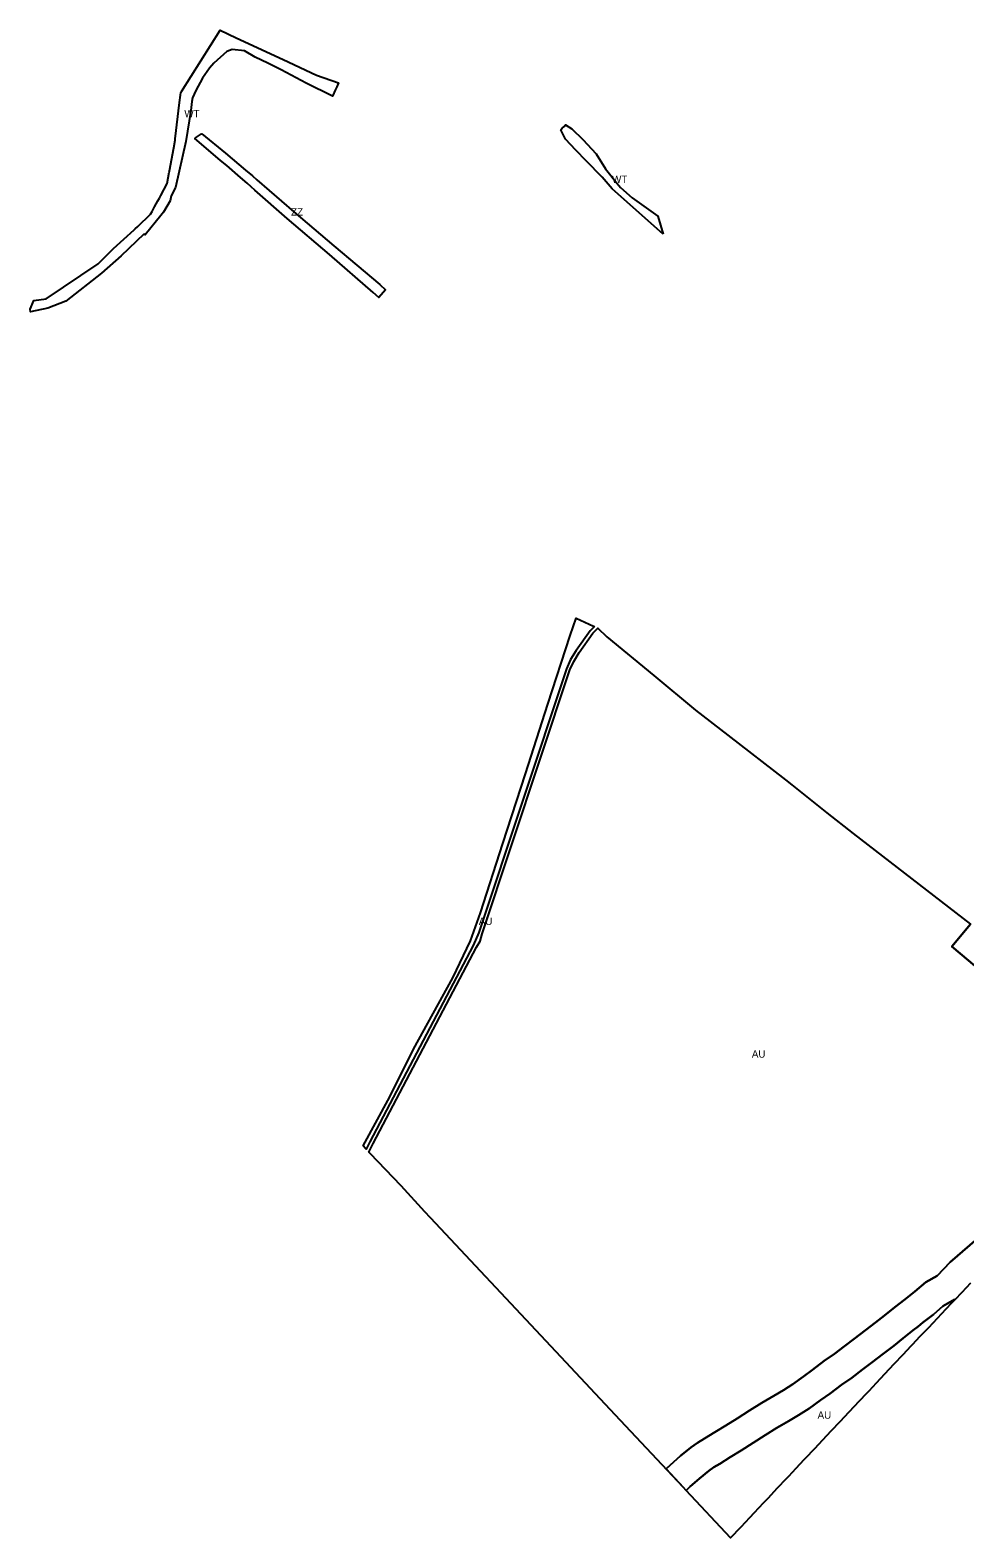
# Model space of a CAD drawing. Extents: x -537068 to -534056, y -1176840 to -1172401.
# Drawn here: x -536870 to -536233, y -1176528 to -1175501 of the extents above; entities that cross this region are included whole.
import ezdxf

# ---------------------------------------------------------------- set-up
doc = ezdxf.new("R2010")
doc.units = 0
for name, color, linetype in [('90640013', 7, 'Continuous'), ('90670013', 7, 'Continuous'), ('90710023', 7, 'Continuous'), ('90750013', 7, 'Continuous')]:
    doc.layers.add(name, color=color, linetype=linetype)

msp = doc.modelspace()

# ---------------------------------------------------------------- linework, layer by layer
at = {"layer": '90640013'}
for points in [[(-536759.14, -1175546.95), (-536759.43, -1175549.31), (-536760.2, -1175555.61), (-536763.62, -1175576.6), (-536770.63, -1175607.96), (-536773.63, -1175613.72), (-536774.37, -1175617.09), (-536778.85, -1175624.83), (-536780.67, -1175627.12), (-536791.22, -1175640.34), (-536792.15, -1175639.9), (-536807.7, -1175654.66), (-536820.95, -1175666.33), (-536845.3, -1175685.5), (-536857.62, -1175690.33), (-536869.36, -1175692.85), (-536869.69, -1175690.99), (-536867.27, -1175684.92), (-536858.75, -1175683.8), (-536823.33, -1175660), (-536822.48, -1175659.15), (-536818.75, -1175655.44), (-536812.82, -1175649.52), (-536798.75, -1175636.8), (-536798, -1175636.09), (-536796.36, -1175634.54), (-536787.59, -1175626.26), (-536786.55, -1175624.33), (-536784.89, -1175621.26), (-536782.61, -1175617.04), (-536781.63, -1175615.22), (-536780.65, -1175613.4), (-536776.23, -1175605.22), (-536774.85, -1175597.57), (-536774.78, -1175597.19), (-536774.66, -1175596.55), (-536771.82, -1175580.92), (-536770.88, -1175575.77), (-536770.77, -1175574.85), (-536767.84, -1175550.16), (-536767.24, -1175545.07), (-536766.92, -1175543.35), (-536766.47, -1175542.55), (-536740.27, -1175500.8), (-536729.21, -1175505.96), (-536697.28, -1175520.87), (-536674.62, -1175531.43), (-536659.47, -1175536.67), (-536660.75, -1175539.52), (-536661.77, -1175541.78), (-536663.39, -1175545.39), (-536663.63, -1175545.89), (-536681.48, -1175536.89), (-536698.55, -1175527.89), (-536707.77, -1175523.22), (-536716.27, -1175519.21), (-536723.7, -1175514.8), (-536732.11, -1175514.02), (-536735.71, -1175515.33), (-536744.58, -1175523.27), (-536747.34, -1175526.78), (-536752.18, -1175533.41), (-536756.67, -1175542.01)], [(-536438.2, -1175639.85), (-536473.11, -1175608.92), (-536479.81, -1175600.97), (-536490.76, -1175589.93), (-536497.76, -1175582.55), (-536504.76, -1175575.16), (-536507.91, -1175568.69), (-536507.02, -1175567.7), (-536505.83, -1175566.38), (-536504.84, -1175565.28), (-536500.44, -1175568.03), (-536492.95, -1175575.29), (-536483.95, -1175585.15), (-536477.54, -1175595.19), (-536469.53, -1175605.27), (-536467.36, -1175608.01), (-536459.44, -1175615.03), (-536441.85, -1175627.58)]]:
    msp.add_lwpolyline(points, close=True, dxfattribs=at)
at = {"layer": '90670013'}
msp.add_lwpolyline([(-536752.82, -1175571.39), (-536752.68, -1175571.49), (-536736.49, -1175584.54), (-536722.97, -1175596.13), (-536718.06, -1175600.17), (-536715.2, -1175602.87), (-536690.07, -1175624.63), (-536662.6, -1175647.71), (-536631.47, -1175674.03), (-536627.48, -1175677.77), (-536632.12, -1175682.89), (-536635.88, -1175679.63), (-536665.73, -1175653.71), (-536694.41, -1175629.09), (-536716.48, -1175609.73), (-536718.97, -1175607.55), (-536721.79, -1175605.09), (-536726.3, -1175601.16), (-536735.66, -1175592.98), (-536739.85, -1175589.55), (-536756.05, -1175575.87), (-536757.55, -1175574.67), (-536756.99, -1175574.28)], close=True, dxfattribs=at)
at = {"layer": '90710023'}
for points in [[(-536220.12, -1176143.12), (-536241.61, -1176125.27), (-536228.83, -1176109.89)], [(-536228.89, -1176354.7), (-536234.72, -1176360.87), (-536239.56, -1176365.98), (-536239.72, -1176365.82), (-536247.63, -1176370.33), (-536254.07, -1176375.9), (-536261.3, -1176381.47), (-536264.5, -1176384.04), (-536267.9, -1176386.65), (-536274.78, -1176392.15), (-536281.14, -1176397.27), (-536288.27, -1176402.67), (-536296.05, -1176408.57), (-536302.46, -1176413.41), (-536309.7, -1176419.02), (-536316.75, -1176423.86), (-536324.52, -1176429.74), (-536330.98, -1176434.34), (-536338.65, -1176439.91), (-536345.91, -1176444.61), (-536352.92, -1176448.6), (-536360.76, -1176453.19), (-536368.72, -1176458.12), (-536376.82, -1176463.49), (-536384.98, -1176468.73), (-536392.59, -1176473.17), (-536399.72, -1176477.63), (-536403.8, -1176480.03), (-536407.11, -1176482.46), (-536413.48, -1176487.6), (-536419.89, -1176493.22), (-536422.6, -1176495.87), (-536424.66, -1176493.67), (-536436.14, -1176481.14), (-536433.48, -1176478.54), (-536426.36, -1176472.29), (-536419.31, -1176466.61), (-536414.82, -1176463.31), (-536410.1, -1176460.53), (-536402.94, -1176456.05), (-536395.43, -1176451.67), (-536387.75, -1176446.74), (-536379.51, -1176441.28), (-536371.08, -1176436.06), (-536362.92, -1176431.28), (-536356.3, -1176427.51), (-536349.97, -1176423.41), (-536342.66, -1176418.1), (-536336.36, -1176413.62), (-536328.45, -1176407.63), (-536321.49, -1176402.86), (-536314.61, -1176397.52), (-536308.12, -1176392.62), (-536300.35, -1176386.73), (-536293.45, -1176381.51), (-536287.3, -1176376.55), (-536280.32, -1176370.97), (-536273.58, -1176365.68), (-536266.72, -1176360.4), (-536259.23, -1176353.92), (-536251.53, -1176349.53), (-536242.72, -1176340.22), (-536115.28, -1176230.23)]]:
    msp.add_lwpolyline(points, dxfattribs=at)
at = {"layer": '90750013'}
for points in [[(-536485.13, -1175907.12), (-536488.05, -1175910.19), (-536497.58, -1175923.45), (-536501.38, -1175929.75), (-536504.09, -1175935.89), (-536563.94, -1176115.77), (-536567.74, -1176124.52), (-536638.12, -1176258.4), (-536640.58, -1176263.38), (-536641.11, -1176262.81), (-536642.71, -1176261.11), (-536624.47, -1176227.58), (-536608.5, -1176195.13), (-536581.56, -1176146.59), (-536569.66, -1176121.36), (-536562.79, -1176102.25), (-536547.42, -1176055.12), (-536532.18, -1176007.54), (-536516.87, -1175960.09), (-536501.59, -1175913.34), (-536497.61, -1175901.43), (-536485.64, -1175906.89)], [(-536422.6, -1176495.87), (-536419.89, -1176493.22), (-536413.48, -1176487.6), (-536407.11, -1176482.46), (-536403.8, -1176480.03), (-536399.72, -1176477.63), (-536392.59, -1176473.17), (-536384.98, -1176468.73), (-536376.82, -1176463.49), (-536368.72, -1176458.12), (-536360.76, -1176453.19), (-536352.92, -1176448.6), (-536345.91, -1176444.61), (-536338.65, -1176439.91), (-536330.98, -1176434.34), (-536324.52, -1176429.74), (-536316.75, -1176423.86), (-536309.7, -1176419.02), (-536302.46, -1176413.41), (-536296.05, -1176408.57), (-536288.27, -1176402.67), (-536281.14, -1176397.27), (-536274.78, -1176392.15), (-536267.9, -1176386.65), (-536264.5, -1176384.04), (-536261.3, -1176381.47), (-536254.07, -1176375.9), (-536247.63, -1176370.33), (-536239.72, -1176365.82), (-536239.56, -1176365.98), (-536241.78, -1176368.33), (-536245.55, -1176372.32), (-536248.46, -1176375.4), (-536251.47, -1176378.58), (-536257.51, -1176384.96), (-536260.46, -1176388.08), (-536263.44, -1176391.23), (-536268.3, -1176396.37), (-536269.36, -1176397.5), (-536274.94, -1176403.42), (-536281.04, -1176409.9), (-536287.42, -1176416.69), (-536293.06, -1176422.68), (-536298.17, -1176428.11), (-536299.32, -1176429.33), (-536305.12, -1176435.49), (-536307.84, -1176438.38), (-536311.84, -1176442.63), (-536317.64, -1176448.79), (-536323.89, -1176455.43), (-536329.6, -1176461.5), (-536335.16, -1176467.41), (-536341.45, -1176474.08), (-536342.38, -1176475.07), (-536347.82, -1176480.86), (-536352.9, -1176486.26), (-536354.21, -1176487.65), (-536360.7, -1176494.54), (-536366.78, -1176501), (-536369.94, -1176504.36), (-536373.27, -1176507.9), (-536376.32, -1176511.14), (-536379.5, -1176514.52), (-536385.42, -1176520.81), (-536385.63, -1176521.03), (-536392.33, -1176528.15)]]:
    msp.add_lwpolyline(points, close=True, dxfattribs=at)
msp.add_lwpolyline([(-536115.28, -1176230.23), (-536242.72, -1176340.22), (-536251.53, -1176349.53), (-536259.23, -1176353.92), (-536266.72, -1176360.4), (-536273.58, -1176365.68), (-536280.32, -1176370.97), (-536287.3, -1176376.55), (-536293.45, -1176381.51), (-536300.35, -1176386.73), (-536308.12, -1176392.62), (-536314.61, -1176397.52), (-536321.49, -1176402.86), (-536328.45, -1176407.63), (-536336.36, -1176413.62), (-536342.66, -1176418.1), (-536349.97, -1176423.41), (-536356.3, -1176427.51), (-536362.92, -1176431.28), (-536371.08, -1176436.06), (-536379.51, -1176441.28), (-536387.75, -1176446.74), (-536395.43, -1176451.67), (-536402.94, -1176456.05), (-536410.1, -1176460.53), (-536414.82, -1176463.31), (-536419.31, -1176466.61), (-536426.36, -1176472.29), (-536433.48, -1176478.54), (-536436.14, -1176481.14), (-536424.66, -1176493.67), (-536470.9, -1176444.37), (-536517.92, -1176394.22), (-536596.72, -1176310.19), (-536600.59, -1176306.07), (-536616.85, -1176288.33), (-536637.95, -1176266.24), (-536638.79, -1176265.29), (-536635.9, -1176259.54), (-536565.48, -1176125.6), (-536562.88, -1176121.54), (-536561.6, -1176116.66), (-536501.76, -1175936.79), (-536499.16, -1175930.91), (-536495.49, -1175924.83), (-536486.12, -1175911.79), (-536482.76, -1175908.24), (-536476.59, -1175914.1), (-536444.55, -1175940.62), (-536416.3, -1175964.17), (-536394.22, -1175981.31), (-536354.83, -1176011.62), (-536350.59, -1176015.06), (-536326.65, -1176034.06), (-536308.86, -1176048.3), (-536228.83, -1176109.89), (-536241.61, -1176125.27), (-536220.12, -1176143.12)], dxfattribs=at)

# ---------------------------------------------------------------- texts
at = {"layer": '90640013'}
for rotation, p in [(0, (-536764.58, -1175560.22)), (360, (-536473.06, -1175604.9))]:
    msp.add_text('WT', height=5, rotation=rotation, dxfattribs=at).set_placement(p)
at = {"layer": '90670013'}
msp.add_text('ZZ', height=5, rotation=360, dxfattribs=at).set_placement((-536691.86, -1175627.14))
at = {"layer": '90750013'}
for p in [(-536563.92, -1176110.55), (-536377.8, -1176200.96), (-536333.01, -1176446.98)]:
    msp.add_text('AU', height=5, rotation=360, dxfattribs=at).set_placement(p)

doc.saveas('drawing.dxf')
